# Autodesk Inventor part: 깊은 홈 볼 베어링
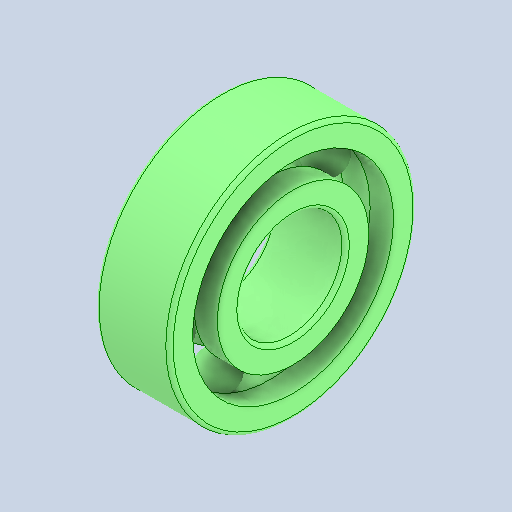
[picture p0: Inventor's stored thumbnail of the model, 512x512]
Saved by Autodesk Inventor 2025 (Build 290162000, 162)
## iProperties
Created: 2026-07
Part Number: 깊은 홈 볼 베어링
Material: 강철, 연강
Description: 깊은 그루브 볼 베어링
Document SubType Name: Modeling
Designer: KDI
Density: 7.86 g/cm^3
Appearance: 기본값
Author: jhkim
Revision Number: 1
Sending System: Autodesk Inventor 2027
Preprocessor: ST-DEVELOPER v20.1
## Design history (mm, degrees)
feature "Solid1"
feature "Solid1:1"
feature "Solid1:2"
feature "Solid1:3"
feature "Solid1:4"
feature "Solid1:5"
feature "Solid1:6"
feature "Solid1:7"
feature "Solid1:8"
node "솔리드1"
node "솔리드2"
node "솔리드3"
node "솔리드4"
node "솔리드5"
node "솔리드6"
node "솔리드7"
node "솔리드8"
node "솔리드9"
